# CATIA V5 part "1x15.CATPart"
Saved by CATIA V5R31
Part number: 1x15_cent
Definition: 15M Beam 4542576/64871
Nomenclature: 15M Beam 4542576/64871
Source: Unknown
Bounding box of the stored display mesh (mm): x -0.1 to 7.103, y -3.6 to 115.6, z 0 to 8
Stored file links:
  C:\Users\super\Desktop\LEGO\TFG-2621\TFG_02621_anejos\1x15.CATPart
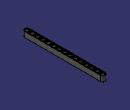
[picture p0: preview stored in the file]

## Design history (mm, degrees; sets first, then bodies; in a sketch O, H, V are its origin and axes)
AxisSystem1: origin (0, 0, 0), X (1, 0, 0), Y (0, 1, 0), Z (0, 0, 1)
Body1 "Body1" (main body)
  Solid1: solid without history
